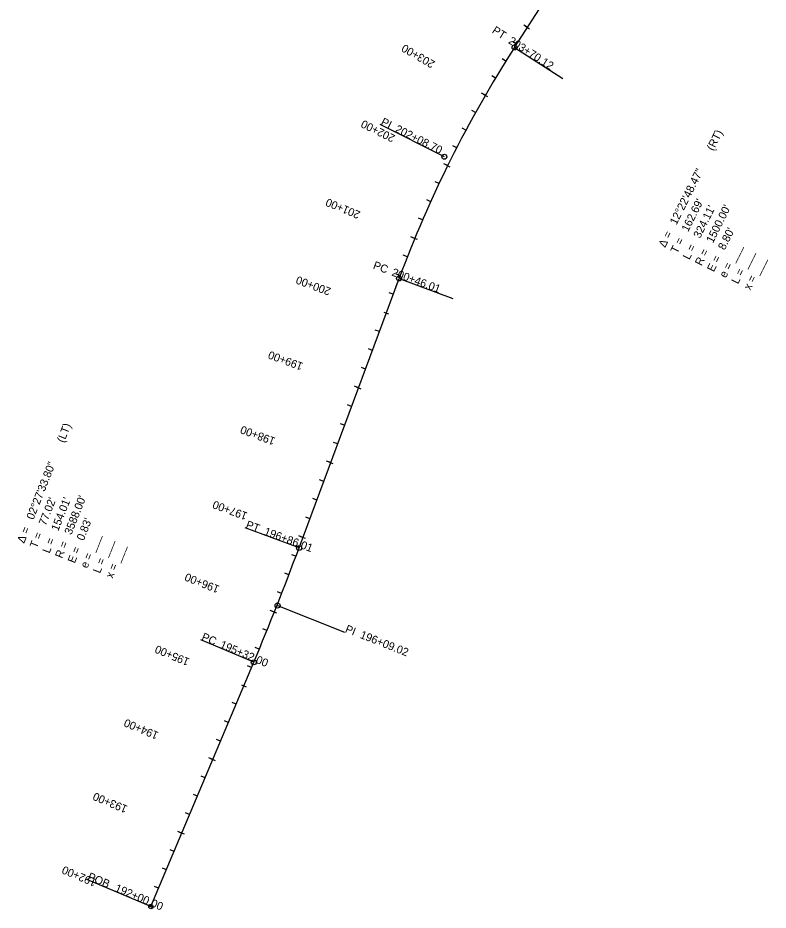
# Model space of a CAD drawing. Extents: x 14118619 to 14120230, y 8668091 to 8670317.
# Drawn here: x 14118619 to 14119559, y 8668091 to 8669208 of the extents above; entities that cross this region are included whole.
import ezdxf

# ---------------------------------------------------------------- set-up
doc = ezdxf.new("R2010")
doc.units = 0
for name, color, linetype in [('PhoBuilding', 7, 'Continuous'), ('PhoDrainageArrow', 7, 'Continuous'), ('PhoEdgeEntranceUnpaved', 7, 'Continuous'), ('PhoEdgeParkingUnpaved', 7, 'Continuous'), ('PhoGuardRail', 7, 'Continuous'), ('PhoRoadPoints', 7, 'Continuous')]:
    doc.layers.add(name, color=color, linetype=linetype)

msp = doc.modelspace()

# ---------------------------------------------------------------- linework, layer by layer
at = {"layer": 'PhoBuilding'}
for p, q in [((14119257.8, 8669196), (14119253.2, 8669199)), ((14119205, 8669111.1), (14119200.3, 8669113.8)), ((14119157.8, 8669022.9), (14119152.9, 8669025.3)), ((14119116.6, 8668931.8), (14119111.6, 8668933.9)), ((14119078, 8668839.5), (14119083.8, 8668837.4)), ((14119046.1, 8668744.7), (14119041, 8668746.6)), ((14119011.3, 8668651), (14119006.1, 8668652.9)), ((14118976.4, 8668557.2), (14118971.3, 8668559.1)), ((14118940.7, 8668463.8), (14118935.6, 8668465.9)), ((14118899.6, 8668372.6), (14118905.3, 8668370.2)), ((14118863.6, 8668279.3), (14118858.6, 8668281.4)), ((14118824.8, 8668187.1), (14118819.8, 8668189.2)), ((14118786, 8668095), (14118781, 8668097.1))]:
    msp.add_line(p, q, dxfattribs=at)
at = {"layer": 'PhoDrainageArrow'}
for p, q in [((14119255.2, 8669197.7), (14119260.3, 8669194.4)), ((14119244.2, 8669175), (14119239.6, 8669178)), ((14119230.8, 8669153.9), (14119226.2, 8669156.8)), ((14119217.8, 8669132.6), (14119213.1, 8669135.4)), ((14119202.4, 8669112.6), (14119207.7, 8669109.5)), ((14119192.7, 8669089.3), (14119187.9, 8669092)), ((14119180.7, 8669067.4), (14119175.9, 8669070)), ((14119169.1, 8669045.3), (14119164.2, 8669047.7)), ((14119155.1, 8669024.3), (14119160.6, 8669021.6)), ((14119147, 8669000.4), (14119142, 8669002.7)), ((14119136.5, 8668977.7), (14119131.5, 8668980)), ((14119126.4, 8668954.9), (14119121.3, 8668957)), ((14119113.8, 8668933), (14119119.5, 8668930.7)), ((14119107.3, 8668908.7), (14119102.2, 8668910.7)), ((14119098.3, 8668885.3), (14119093.2, 8668887.2)), ((14119089.6, 8668861.9), (14119084.5, 8668863.8)), ((14119078, 8668839.5), (14119083.8, 8668837.4)), ((14119072.2, 8668815), (14119067.1, 8668816.9)), ((14119063.5, 8668791.6), (14119058.4, 8668793.5)), ((14119054.8, 8668768.1), (14119049.7, 8668770)), ((14119043.2, 8668745.8), (14119048.9, 8668743.6)), ((14119037.4, 8668721.3), (14119032.3, 8668723.2)), ((14119028.7, 8668697.8), (14119023.5, 8668699.7)), ((14119020, 8668674.4), (14119014.8, 8668676.3)), ((14119008.4, 8668652), (14119014.1, 8668649.9)), ((14119002.6, 8668627.5), (14118997.4, 8668629.4)), ((14118993.8, 8668604.1), (14118988.7, 8668606)), ((14118985.1, 8668580.7), (14118980, 8668582.6)), ((14118973.6, 8668558.3), (14118979.3, 8668556.2)), ((14118967.7, 8668533.8), (14118962.6, 8668535.7)), ((14118958.9, 8668510.4), (14118953.8, 8668512.4)), ((14118949.8, 8668487.1), (14118944.8, 8668489.1)), ((14118937.8, 8668465), (14118943.5, 8668462.7)), ((14118931.3, 8668440.7), (14118926.3, 8668442.7)), ((14118921.8, 8668417.5), (14118916.8, 8668419.6)), ((14118912.1, 8668394.5), (14118907.1, 8668396.6)), ((14118899.6, 8668372.6), (14118905.3, 8668370.2)), ((14118892.7, 8668348.4), (14118887.7, 8668350.5)), ((14118883, 8668325.4), (14118878, 8668327.5)), ((14118873.3, 8668302.3), (14118868.3, 8668304.4)), ((14118860.8, 8668280.5), (14118866.4, 8668278.1)), ((14118853.9, 8668256.2), (14118848.9, 8668258.4)), ((14118844.2, 8668233.2), (14118839.2, 8668235.3)), ((14118834.5, 8668210.2), (14118829.5, 8668212.3)), ((14118822, 8668188.3), (14118827.6, 8668185.9)), ((14118815.1, 8668164.1), (14118810.1, 8668166.2)), ((14118805.4, 8668141), (14118800.4, 8668143.2)), ((14118795.7, 8668118), (14118790.7, 8668120.1)), ((14118783.2, 8668096.1), (14118788.8, 8668093.8))]:
    msp.add_line(p, q, dxfattribs=at)
at = {"layer": 'PhoEdgeEntranceUnpaved'}
for p, q in [((14118971.6, 8668544.1), (14119096.9, 8668881.6)), ((14118786, 8668095), (14118914.9, 8668400.9))]:
    msp.add_line(p, q, dxfattribs=at)
for centre, radius, start, end in [((14120503, 8668359.3), 1500, 147.2426, 159.6227), ((14115608.1, 8669793.5), 3588, 337.1633, 339.6227)]:
    msp.add_arc(centre, radius, start, end, dxfattribs=at)
at = {"layer": 'PhoEdgeParkingUnpaved'}
for p, q in [((14119241.6, 8669170.9), (14119302.1, 8669131.9)), ((14119153.6, 8669034.1), (14119073.1, 8669074.3)), ((14119096.9, 8668881.6), (14119164.4, 8668856.5)), ((14118971.6, 8668544.1), (14118904.1, 8668569.2)), ((14118944.7, 8668471.9), (14119028.4, 8668438.8)), ((14118914.9, 8668400.9), (14118848.5, 8668428.9)), ((14118786, 8668095), (14118705.8, 8668128.7))]:
    msp.add_line(p, q, dxfattribs=at)
for centre, radius in [((14119241.6, 8669170.9), 3.12), ((14119153.6, 8669034.1), 3.12), ((14119096.9, 8668881.6), 3.12), ((14118971.6, 8668544.1), 3.12), ((14118944.7, 8668471.9), 3.12), ((14118914.9, 8668400.9), 3.12), ((14118786, 8668095), 2.67)]:
    msp.add_circle(centre, radius, dxfattribs=at)
at = {"layer": 'PhoGuardRail'}
for p, q in [((14119241.6, 8669170.9), (14119444.8, 8669486.7)), ((14118971.6, 8668544.1), (14119096.9, 8668881.6)), ((14118786, 8668095), (14118914.9, 8668400.9))]:
    msp.add_line(p, q, dxfattribs=at)
for centre, radius, start, end in [((14120503, 8668359.3), 1500, 147.2426, 159.6227), ((14115608.1, 8669793.5), 3588, 337.1633, 339.6227)]:
    msp.add_arc(centre, radius, start, end, dxfattribs=at)
at = {"layer": 'PhoRoadPoints'}
for p, q in [((14119241.6, 8669170.9), (14119444.8, 8669486.7)), ((14119092.9, 8668870.9), (14119096.9, 8668881.6))]:
    msp.add_line(p, q, dxfattribs=at)
msp.add_arc((14120503, 8668359.3), 1500, 147.2426, 159.6227, dxfattribs=at)

# ---------------------------------------------------------------- texts
at = {"layer": 'PhoBuilding'}
for s, rotation, p in [('200+00', 159.6227, (14119012.3, 8668869.3)), ('195+00', 157.1633, (14118835.3, 8668405.2))]:
    msp.add_text(s, height=10.02, rotation=rotation, dxfattribs=at).set_placement(p)
at = {"layer": 'PhoDrainageArrow'}
for s, rotation, p in [('203+00', 149.9211, (14119142.7, 8669153)), ('202+00', 153.7408, (14119092.8, 8669060.6)), ('201+00', 157.5605, (14119049.2, 8668965.1)), ('200+00', 159.6227, (14119012.3, 8668869.3)), ('199+00', 159.6227, (14118977.5, 8668775.5)), ('198+00', 159.6227, (14118942.7, 8668681.8)), ('197+00', 159.6227, (14118907.9, 8668588)), ('196+00', 158.2492, (14118872.8, 8668496.3)), ('195+00', 157.1633, (14118835.3, 8668405.2)), ('194+00', 157.1633, (14118796.5, 8668313)), ('193+00', 157.1633, (14118757.6, 8668220.8)), ('192+00', 157.1633, (14118718.8, 8668128.7))]:
    msp.add_text(s, height=10.02, rotation=rotation, dxfattribs=at).set_placement(p)
at = {"layer": 'PhoEdgeParkingUnpaved'}
for s, rotation, p in [('PT', 327.2426, (14119212.5, 8669189.9)), ('203+70.12', 327.2426, (14119232.9, 8669176.8)), ('PI ', 333.4326, (14119073.2, 8669074.5)), ('202+08.70', 333.4326, (14119091, 8669065.6)), (' (RT)', 63.4326, (14119489, 8669037.4)), ('12°22\'48.47"', 63.4326, (14119444.3, 8668948)), ("162.69'", 63.4326, (14119459, 8668939.2)), ("324.11'", 63.4326, (14119473.9, 8668931.1)), ("1500.00'", 63.4326, (14119490, 8668925.1)), ('Δ = ', 63.4326, (14119430.1, 8668919.6)), ("8.80'", 63.4326, (14119504.7, 8668916.4)), ('T = ', 63.4326, (14119445.3, 8668912)), ('L = ', 63.4326, (14119460.6, 8668904.4)), ('R = ', 63.4326, (14119475.8, 8668896.7)), ('e = ___ ', 63.4326, (14119506.3, 8668881.5)), ('E = ', 63.4326, (14119491.1, 8668889.1)), ('L = ___', 63.4326, (14119521.5, 8668873.9)), ('PC', 339.6227, (14119063.5, 8668894.2)), ('x = ___', 63.4326, (14119536.8, 8668866.3)), ('200+46.01', 339.6227, (14119086.9, 8668885.5)), (' (LT)', 68.393, (14118675.8, 8668671.7)), ('02°27\'33.80"', 68.393, (14118638.9, 8668578.8)), ("77.02'", 68.393, (14118654.3, 8668571.3)), ("154.01'", 68.393, (14118669.9, 8668564.5)), ("3588.00'", 68.393, (14118686.4, 8668559.9)), ("0.83'", 68.393, (14118701.8, 8668552.5)), ('Δ = ', 68.393, (14118627.2, 8668549.3)), ('PT', 339.6227, (14118904.1, 8668569.4)), ('T = ', 68.393, (14118643.1, 8668543)), ('e = ___ ', 68.393, (14118706.4, 8668517.9)), ('196+86.01', 339.6227, (14118926.9, 8668560.9)), ('L = ', 68.393, (14118658.9, 8668536.7)), ('R = ', 68.393, (14118674.8, 8668530.4)), ('L = ___', 68.393, (14118722.3, 8668511.6)), ('E = ', 68.393, (14118690.6, 8668524.2)), ('x = ___', 68.393, (14118738.1, 8668505.4)), ('PI ', 338.393, (14119028.5, 8668438.9)), ('PC', 337.1633, (14118848.6, 8668429.1)), ('196+09.02', 338.393, (14119047.1, 8668431.6)), ('195+32.00', 337.1633, (14118871.6, 8668419.4)), ('POB ', 337.1633, (14118705.9, 8668128.9)), ('192+00.00', 337.1633, (14118740, 8668114.5))]:
    msp.add_text(s, height=10.02, rotation=rotation, dxfattribs=at).set_placement(p)

doc.saveas('drawing.dxf')
